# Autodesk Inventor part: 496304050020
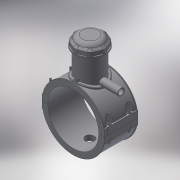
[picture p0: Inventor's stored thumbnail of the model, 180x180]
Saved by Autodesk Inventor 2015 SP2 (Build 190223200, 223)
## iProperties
Created: 2017-07
Part Number: 496304050020
Material: Generic
Description: PLASSON TAPPING SADDLE 50x20
Document SubType Name: Modeling
Designer: KIM
Mass: 167.091 g
Surface Area: 713.979 cm^2
Volume: 167.091 cm^3
Density: 1 g/cm^3
Appearance: Default
Author: KIM
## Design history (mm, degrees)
derived "496304.ipt"
feature "Solid1::496304.ipt"
feature "Solid2::496304.ipt"
feature "Solid4::496304.ipt"
feature "Solid5::496304.ipt"
tag "TaggingFeature1"
body "Solid1"
body "Solid2"
other parameters: "d2" = 76, "d3" = 12.5, "d5" = 0, "d6" = 0.1, "d8" = 0, "d19" = 6, "d20" = 6, "d23" = 0, "d26" = 0, "d29" = 3, "d30" = 16.66667, "d31" = 6, "d32" = 0, "d33" = 0, "d34" = 0.6, "d40" = 33.8, "d41" = 45, "d43" = 0, "d45" = 0, "d47" = 92.5, "d70" = 15, "d72" = 0, "d73" = 6, "d75" = 5, "d76" = 0, "d77" = 2.5, "d78" = 55, "d79" = 15, "d82" = 5 deg, "d84" = 4, "d85" = 14, "d86" = 0, "d87" = 3, "d88" = 0, "d89" = 1, "d90" = 1, "d92" = 0, "d93" = 0.5, "d94" = 26.31579, "d96" = 66.3, "d97" = 2, "d98" = 0, "d102" = 0.5, "d120" = 140 deg, "d121" = 24.228, "d122" = 20 deg, "d124" = 39, "d126" = 0, "d143" = 51.5, "d145" = 11.53846, "d149" = 0.75, "d150" = 12.69231, "d154" = 0, "d156" = 32.5, "d157" = 160 deg, "d159" = 3, "d161" = 0.75, "d163" = 0, "d164" = 25, "d167" = 5, "d168" = 31.70732, "d170" = 3.375, "d172" = 0, "d173" = 1, "d175" = 25, "d176" = 20 deg, "d177" = 3.5, "d178" = 15, "d180" = 0, "d183" = 6, "d184" = 2.8, "d185" = 32.5, "d186" = 32.5, "d187" = 32.5, "d188" = 4.5, "d189" = 3.5, "d190" = 0, "d191" = 48.75, "d193" = 6.3, "d194" = 3.5, "d195" = 90 deg, "d197" = 0, "d199" = 0, "d200" = 7.5, "d202" = 0, "d203" = 98, "d204" = 42.75, "d205" = 31.5, "d206" = 38.25, "d207" = 73.5, "d208" = 76.44, "d209" = 91.14, "d210" = 38.7, "d211" = 45, "d212" = 36, "d213" = -2.7, "d216" = 0, "d217" = 5, "d218" = 5, "d219" = 1, "d224" = 0, "d230" = 3, "d233" = 6, "d236" = 38, "d238" = 6.02433, "d243" = 6, "d247" = 6, "d248" = 6, "d249" = 6, "d253" = 6, "d254" = 6, "d256" = 6, "d257" = 32, "d259" = 16, "d262" = 8, "d263" = 76, "d265" = 0, "d267" = 13.00006, "d268" = 2.60001, "d269" = 2.60001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
